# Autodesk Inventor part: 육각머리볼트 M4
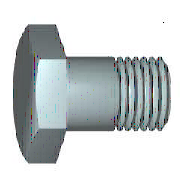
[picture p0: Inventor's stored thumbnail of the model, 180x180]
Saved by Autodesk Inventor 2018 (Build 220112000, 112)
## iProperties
IsCustomPart: 1
Created: 2012-02
Part Number: 육각머리볼트 M4
Material: 스테인리스강
Description: 6각 머리 볼트 및 6각 머리 나사
Document SubType Name: Modeling
Standard: KS B 1002
Designer: mduedu
Standards Organization: KS
Language: ko-KR
Size Designation: A + B M4 x 10
Categories: <MemberInstance><Categories><Category DisplayName="조임쇠" InternalName="e4da775c-781d-43d5-af7c-5136215cf5a6" Mnemonic="FSTN"><Category DisplayName="볼트" InternalN
Density: 8.08 g/cm^3
Mass: 1.91435 g
Surface Area: 2.70732 cm^2
Volume: 0.236925 cm^3
Appearance: 반광택
Author: mduedu
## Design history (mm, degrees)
sketch "스케치1"
  geometry: L1 (0, 2.94)-(0, 2); L2 (2.1, 2)-(10, 2); L3 (10, 2)-(10, 0); L4 (10, 0)-(-0.4, 0); L5 (-2.48, 0)-(12.08, 0) reference; L6 (-0.4, 0)-(-0.4, 2.94); L7 (-0.4, 2.94)-(0, 2.94); L8 (2.1, 2)-(1.67, 2); L9 (1.67, 2)-(0, 2); L10 (0, -0.588)-(0, 3.528) reference
  constraints: 16 end point, 2 collinear, 2 perpendicular, 1 parallel
  dimensions: "d0" = 10 distance between parallel lines of L3 L1 (= NLG); "d1" = 7.9 distance from line of L2.start L3 (= GEL); "d2" = 4 diameter of L2 L4 (= GD); "d9" = 0.4001 distance between parallel lines of L6 L1 (computed from SD); "d10" = 5.88 diameter of L7 L4 (= SD2); "d13" = 0.42952 distance of L2.start L8.end (computed from GAL); "d14" = 4 diameter of L9 L4 (= BDM)
revolve "본체" sketch "스케치1" stored, may be unused: angle "d12" = 90 deg
sketch "스케치2"
  geometry: L1 (0, 4.041)-(3.5, 2.021); L2 (3.5, 2.021)-(3.5, -2.021); L3 (3.5, -2.021)-(0, -4.041); L4 (0, -4.041)-(-3.5, -2.021); L5 (-3.5, -2.021)-(-3.5, 2.021); L6 (-3.5, 2.021)-(0, 4.041); 2 further points
  constraints: 12 end point, 1 coincident, 1 vertical, 11 other
  dimensions: "d11" = 7 distance between parallel lines of L5 L2 (= SW)
extrude "머리" join sketch "스케치2" distance "d3" = 2.4 (= KOH - SD); taper "d4" = 0 deg
sketch "스케치4"
  geometry: L1 (-2.8, 3.5)-(-2.8, 4.041); L2 (-2.8, 4.041)-(-2.487, 4.041); L3 (-2.487, 4.041)-(-2.8, 3.5); L4 (-3.28, 0)-(0.08, 0) reference; L5 (-0.4, 4.041)-(-2.8, 4.041) reference; L6 (-2.8, 2.021)-(-2.8, 4.041) reference
  constraints: 6 end point, 2 collinear, 1 perpendicular, 1 vertical
  dimensions: "d5" = 30 deg angle of L3 L1 (= ANG1); "d19" = 7 diameter of L1.start L4 (= SW0)
revolve "모따기1" sketch "스케치4" stored, may be unused: angle "d21" = 90 deg
workplane "Work Plane1"
body "Solid1"
feature "스레드" dims "d15" = 7.9 (= GEL), "d16" = 0
chamfer "모따기2" distance "d6" = 0.42941 (= -0.5 x SPD + 0.5 x GD); stored, may be unused: second distance "d7" = 0.42952 (computed from GUL), angle "d55" = 45 deg
other parameters: "NLG" = 10 [user parameter; used in 1 equation term], "GD" = 4 (= NND) [user parameter; used in 2 equation terms], "BDM" = 4 (= NND) [user parameter; used in 1 equation term], "KOH" = 2.8 [user parameter; used in 1 equation term], "GEL" = 7.9 [user parameter; used in 2 equation terms], "SW" = 7 [user parameter; used in 3 equation terms], "SW0" = 7 (= SW) [user parameter; used in 1 equation term], "SPD" = 3.14117 (= NND - 1.2269 x PTC) [user parameter; used in 1 equation term], "SD2" = 5.88 (= SDH) [user parameter; used in 1 equation term], "SD" = 0.4 [user parameter; used in 2 equation terms], "ANG1" = 30 deg [user parameter; used in 1 equation term], "GAL" = 0.42941 (= 0.61345 x PTC) [user parameter; used in 1 equation term], "GUL" = 0.42941 (= 0.61345 x PTC) [user parameter; used in 1 equation term], "d8" = 0, "RR" = 0.2 [user parameter], "d57" = 0, "d58" = 0, "TPU" = 14.28571 (computed from PTC) [user parameter], "GD1" = 3.14117 (= THREADDIA - 1.2269 x PTC) [user parameter], "THREADDIA" = 4 [user parameter; used in 1 equation term], "SDH" = 5.88 [user parameter; used in 1 equation term], "SDHG" = 2.1 [user parameter], "TOA" = 30 deg [user parameter], "PTC" = 0.7 [user parameter; used in 5 equation terms], "NND" = 4 [user parameter; used in 3 equation terms], "E0" = 8.085 (= 1.155 x SW) [user parameter]
